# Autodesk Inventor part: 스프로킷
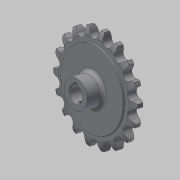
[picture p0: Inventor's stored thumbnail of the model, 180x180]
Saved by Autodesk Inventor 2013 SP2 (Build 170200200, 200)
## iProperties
Created: 2016-03
Part Number: 스프로킷
Material: 강철, 탄소
Document SubType Name: Modeling
Designer: mduedu
Density: 7.87 g/cm^3
Mass: 301.818 g
Surface Area: 124.882 cm^2
Volume: 38.3505 cm^3
Author: mduedu
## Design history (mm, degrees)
sketch "스케치1"
  geometry: L1 (0, 5)-(29.5, 5); L2 (29.5, 5)-(29.5, 4.1); L3 (30, 3.6)-(33.625, 3.6); L4 (40, 2)-(40, 0); L5 (40, 0)-(0, 0); L6 (0, 0)-(0, 5); L7 (0, -5)-(29.5, -5); L8 (29.5, -5)-(29.5, -4.1); L9 (30, -3.6)-(33.625, -3.6); L10 (40, -2)-(40, 0); L11 (0, 0)-(0, -5); A1 r 13.5 centre (33.625, -9.9) between (40, 2) and (33.625, 3.6); A2 r 13.5 centre (33.625, 9.9) between (33.625, -3.6) and (40, -2); A3 r 0.5 centre (30, 4.1) between (29.5, 4.1) and (30, 3.6); A4 r 0.5 centre (30, -4.1) between (30, -3.6) and (29.5, -4.1); 2 further points
  constraints: 22 end point, 8 point on circle, 6 symmetric about line, 5 tangent, 4 centre point, 4 parallel, 4 point on line, 1 equal radius, 1 horizontal, 1 perpendicular, 1 other
  dimensions: "d0" = 80 diameter of L4 L6; "d2" = 59 diameter of L2 L6; "d3" = 1.6 vertical distance of L4.start L3.end; "d4" = 3.6 distance from line of L4.end L3; "d5" = 5 distance between parallel lines of L5 L1; "d6" = 13.5 radius of A1; "d15" = 0.5 radius of A3
revolve "회전1" sketch "스케치1" stored, may be unused: angle "d7" = 90 deg
sketch "스케치2" dims "d8" = 65.2, "d11" = 80
  geometry: L1 (0, 0)-(0, 32.6); A1 r 36.57 centre (0, 0) between (-16.231, 32.771) and (0, 36.57); A2 r 3.97 centre (0, 36.57) between (-3.866, 35.665) and (0, 32.6); A3 r 12.7 centre (-16.231, 32.771) between (-3.866, 35.665) and (-5.534, 39.615); A4 r 12.7 centre (16.231, 32.771) between (5.534, 39.615) and (3.866, 35.665); A5 r 3.97 centre (0, 36.57) between (0, 32.6) and (3.866, 35.665); A6 r 40 centre (0, 0) between (5.534, 39.615) and (-5.534, 39.615); 2 further points
  constraints: 12 point on circle, 6 centre point, 4 coincident, 3 symmetric about line, 2 end point, 1 point on line, 1 tangent, 1 vertical, 1 vertical alignment, 7 other
  dimensions: "d10" = 73.14 diameter of A1; "d12" = 12.7 radius of A3
extrude "돌출1" cut sketch "스케치2" stored distance "d13" = 10; taper "d14" = 0 deg
sketch "스케치3"
  geometry: C1 r 11 at (0, 0); 1 further point
  constraints: 1 centre point, 1 coincident
  dimensions: "d19" = 22 diameter of C1
extrude "돌출2" join sketch "스케치3" distance "d20" = 13; taper "d21" = 0 deg
fillet "모깎기1" dims "d22" = 3
sketch "스케치4"
  geometry: L1 (-2, 0)-(2, 0); L2 (2, 0)-(2, 7.8); L3 (2, 7.8)-(-2, 7.8); L4 (-2, 7.8)-(-2, 0); C1 r 6 at (0, 0); 2 further points
  constraints: 8 end point, 2 coincident, 2 parallel, 1 centre point, 1 horizontal, 1 midpoint, 1 perpendicular
  dimensions: "d23" = 12 diameter of C1; "d25" = 4 distance of L2.end L3.end; "d26" = 7.8 distance of L1.end L2.end
extrude "돌출3" cut sketch "스케치4" stored distance "d27" = 8; taper "d28" = 0 deg
chamfer "모따기1" distance "d29" = 0.5; stored, may be unused: second distance "d30" = 2, angle "d31" = 45 deg
node "작업 평면1"
sketch "스케치5"
  geometry: L1 (11, 13)-(-11, 13) reference; 2 further points
  constraints: 1 vertical alignment
  dimensions: "d32" = 4 distance from line of point (0, 9) L1
hole "구멍1" sketch "스케치5" at (0, 9) diameter "d33" = 2.459; stored, may be unused: countersink angle "d37" = 90 deg, drill point angle "d39" = 118 deg; dims "d34" = 6, "d35" = 4, "d36" = 2, "d38" = 8
node "솔리드1"
pattern_circular "원형 패턴1" dims angle "d17" = 360 deg
